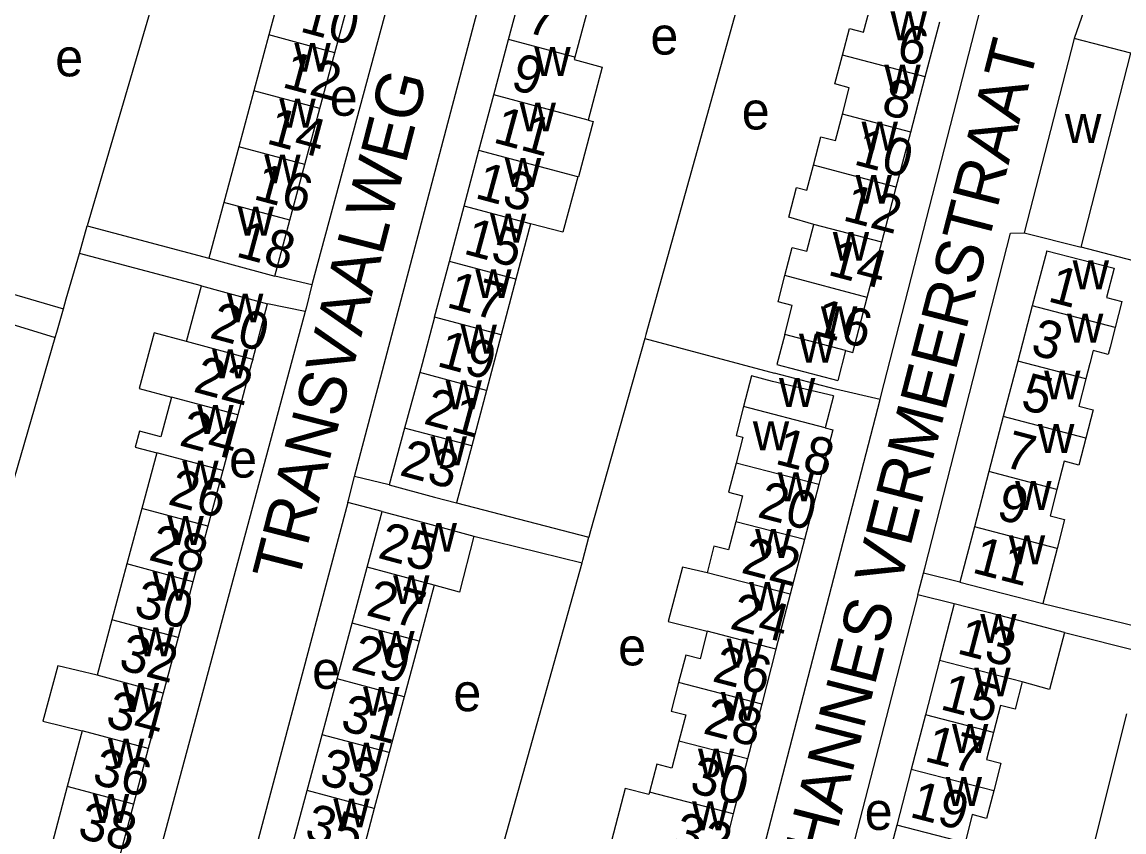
# Model space of a CAD drawing. Extents: x 163012 to 165277, y 382513 to 383987.
# Drawn here: x 163795.3 to 163912.4, y 383200.2 to 383286.3 of the extents above; entities that cross this region are included whole.
import ezdxf

# ---------------------------------------------------------------- set-up
doc = ezdxf.new("R2010")
doc.units = 0
for name, color, linetype in [('BLT_Basislijn', 7, 'Continuous'), ('BLT_Bebouwing', 7, 'Continuous'), ('BLT_Centroide', 7, 'Continuous'), ('BLT_Huisnummer', 7, 'Continuous'), ('BLT_Huisnummer_ tussenligend', 7, 'Continuous'), ('BLT_Onderverdeling_panden', 7, 'Continuous'), ('BLT_Straatnaam', 7, 'Continuous')]:
    doc.layers.add(name, color=color, linetype=linetype)

msp = doc.modelspace()

# ---------------------------------------------------------------- linework, layer by layer
at = {"layer": 'BLT_Basislijn'}
for p, q in [((163817.44, 383316.53), (163802.21, 383264.65)), ((163909.37, 383291.03), (163907.14, 383284.56)), ((163801.39, 383261.7), (163802.21, 383264.65)), ((163802.21, 383264.65), (163815.15, 383261.2)), ((163814.35, 383258.26), (163801.39, 383261.7)), ((163915.64, 383260.36), (163907.87, 383262.37)), ((163826.11, 383258.39), (163822.16, 383259.31)), ((163789.27, 383258.89), (163799.68, 383255.82)), ((163785.34, 383256.88), (163798.81, 383252.77)), ((163825.38, 383255.54), (163821.4, 383256.37)), ((163785.09, 383205.63), (163798.81, 383252.77)), ((163861.49, 383252.69), (163875.3, 383248.99)), ((163834.31, 383237.11), (163830.64, 383238.01)), ((163833.57, 383234.29), (163829.92, 383235.25)), ((163841.47, 383235.19), (163855.55, 383231.55)), ((163843.33, 383231.67), (163854.82, 383228.82)), ((163840.86, 383178.81), (163854.82, 383228.82)), ((163894.99, 383226.78), (163891.12, 383227.74)), ((163894.39, 383224.46), (163890.52, 383225.42)), ((163903.81, 383224.49), (163915.06, 383221.77)), ((163906.11, 383221.42), (163914.43, 383219.32)), ((163909.31, 383199.05), (163912.74, 383212.77))]:
    msp.add_line(p, q, dxfattribs=at)
for points in [[(163840.47, 383311.66), (163826.38, 383259.43), (163826.11, 383258.39)], [(163830.64, 383238.01), (163830.81, 383238.67), (163849.46, 383309.26)], [(163875.6, 383303.33), (163861.61, 383253.11), (163861.49, 383252.69)], [(163886.51, 383246.19), (163886.63, 383246.66), (163898.8, 383294.11), (163899.25, 383297.48)], [(163891.12, 383227.74), (163891.25, 383228.24), (163900.39, 383263.88), (163901.83, 383263.92)], [(163799.68, 383255.82), (163799.99, 383256.88), (163801.39, 383261.7)], [(163826.11, 383258.39), (163825.48, 383255.9), (163825.38, 383255.54)], [(163798.81, 383252.77), (163798.98, 383253.35), (163799.68, 383255.82)], [(163825.38, 383255.54), (163806.41, 383184.98), (163806.33, 383184.51)], [(163861.49, 383252.69), (163855.73, 383232.22), (163855.55, 383231.55)], [(163886.51, 383246.19), (163881.76, 383247.29), (163875.3, 383248.99)], [(163867.61, 383171.92), (163867.73, 383172.49), (163869.27, 383179.64), (163886.51, 383246.19)], [(163829.92, 383235.25), (163829.99, 383235.49), (163830.64, 383238.01)], [(163829.92, 383235.25), (163815.82, 383182.22), (163815.72, 383181.65)], [(163854.82, 383228.82), (163854.9, 383229.11), (163855.55, 383231.55)], [(163890.52, 383225.42), (163890.6, 383225.71), (163891.12, 383227.74)], [(163890.52, 383225.42), (163878.52, 383178.89), (163878.45, 383178.55)]]:
    msp.add_lwpolyline(points, dxfattribs=at)
at = {"layer": 'BLT_Bebouwing'}
for p, q in [((163823.12, 383290.88), (163821.53, 383284.95)), ((163847.01, 383284.48), (163848.58, 383290.38)), ((163828.54, 383283.06), (163830.14, 383289)), ((163891.31, 383280.48), (163892.85, 383286.34)), ((163821.53, 383284.95), (163819.93, 383279.01)), ((163845.43, 383278.57), (163847.01, 383284.48)), ((163907.14, 383284.56), (163901.83, 383263.92)), ((163826.94, 383277.12), (163828.54, 383283.06)), ((163889.77, 383274.62), (163891.31, 383280.48)), ((163819.93, 383279.01), (163818.34, 383273.07)), ((163843.86, 383272.67), (163845.43, 383278.57)), ((163825.35, 383271.19), (163826.94, 383277.12)), ((163888.22, 383268.77), (163889.77, 383274.62)), ((163818.34, 383273.07), (163816.74, 383267.14)), ((163842.29, 383266.76), (163843.86, 383272.67)), ((163823.75, 383265.25), (163825.35, 383271.19)), ((163886.68, 383262.91), (163888.22, 383268.77)), ((163816.74, 383267.14), (163815.15, 383261.2)), ((163840.72, 383260.86), (163842.29, 383266.76)), ((163822.16, 383259.31), (163823.75, 383265.25)), ((163901.83, 383263.92), (163907.87, 383262.37)), ((163885.14, 383257.05), (163886.68, 383262.91)), ((163904.23, 383262.01), (163902.69, 383256.14)), ((163839.15, 383254.95), (163840.72, 383260.86)), ((163812.76, 383252.35), (163814.35, 383258.26)), ((163819.81, 383250.46), (163821.4, 383256.37)), ((163902.69, 383256.14), (163901.15, 383250.27)), ((163882.84, 383251.4), (163882, 383248.2)), ((163901.15, 383250.27), (163899.61, 383244.4)), ((163837.57, 383249.05), (163835.96, 383243.15)), ((163881.57, 383246.57), (163880.68, 383243.19)), ((163818.22, 383244.55), (163816.64, 383238.64)), ((163899.61, 383244.4), (163898.07, 383238.53)), ((163835.96, 383243.15), (163834.31, 383237.11)), ((163809.6, 383240.53), (163808.01, 383234.61)), ((163843.1, 383241.25), (163841.47, 383235.19)), ((163816.64, 383238.64), (163815.05, 383232.72)), ((163898.07, 383238.53), (163896.53, 383232.65)), ((163879.98, 383237.14), (163878.47, 383231.31)), ((163808.01, 383234.61), (163806.43, 383228.7)), ((163831.98, 383228.36), (163833.57, 383234.29)), ((163815.05, 383232.72), (163813.46, 383226.81)), ((163896.53, 383232.65), (163894.99, 383226.78)), ((163878.47, 383231.31), (163876.95, 383225.48)), ((163806.43, 383228.7), (163804.85, 383222.78)), ((163830.39, 383222.42), (163831.98, 383228.36)), ((163813.46, 383226.81), (163811.88, 383220.9)), ((163839.11, 383226.45), (163837.51, 383220.51)), ((163876.95, 383225.48), (163875.44, 383219.64)), ((163894.39, 383224.46), (163892.83, 383218.45)), ((163804.85, 383222.78), (163803.26, 383216.87)), ((163828.79, 383216.49), (163830.39, 383222.42)), ((163811.88, 383220.9), (163810.29, 383214.98)), ((163837.51, 383220.51), (163835.92, 383214.58)), ((163875.44, 383219.64), (163873.92, 383213.81)), ((163892.83, 383218.45), (163891.33, 383212.67)), ((163827.2, 383210.55), (163828.79, 383216.49)), ((163810.29, 383214.98), (163808.71, 383209.07)), ((163835.92, 383214.58), (163834.33, 383208.64)), ((163873.92, 383213.81), (163872.41, 383207.97)), ((163891.33, 383212.67), (163889.82, 383206.86)), ((163801.68, 383210.96), (163800.1, 383205.04)), ((163825.61, 383204.62), (163827.2, 383210.55)), ((163808.71, 383209.07), (163807.12, 383203.16)), ((163834.33, 383208.64), (163832.74, 383202.7)), ((163872.41, 383207.97), (163870.89, 383202.14)), ((163889.82, 383206.86), (163888.28, 383200.94)), ((163800.1, 383205.04), (163798.51, 383199.13)), ((163824.02, 383198.68), (163825.61, 383204.62)), ((163807.12, 383203.16), (163805.54, 383197.24)), ((163832.74, 383202.7), (163831.14, 383196.77)), ((163870.89, 383202.14), (163869.38, 383196.31)), ((163888.28, 383200.94), (163886.8, 383195.26))]:
    msp.add_line(p, q, dxfattribs=at)
for points in [[(163855.64, 383288.5), (163854.07, 383282.6)], [(163882.5, 383282.8), (163883.26, 383285.65), (163884.76, 383285.25), (163885.55, 383288.26)], [(163907.87, 383262.37), (163913.18, 383283.01), (163907.14, 383284.56)], [(163854.07, 383282.6), (163854, 383282.33), (163856.98, 383281.54), (163855.49, 383275.89)], [(163882.51, 383276.53), (163883.24, 383279.34), (163881.7, 383279.74), (163882.5, 383282.8)], [(163855.49, 383275.89), (163856.02, 383275.75), (163854.45, 383269.85), (163854.36, 383269.87)], [(163879.42, 383271.09), (163880.22, 383274.13), (163880.64, 383274.02), (163881.77, 383273.72), (163882.51, 383276.53)], [(163879.46, 383264.81), (163876.8, 383265.59), (163877.62, 383268.72), (163878.72, 383268.43), (163879.42, 383271.09)], [(163854.36, 383269.87), (163852.79, 383263.97), (163849.36, 383264.88)], [(163849.36, 383264.88), (163847.79, 383258.97)], [(163876.39, 383259.36), (163877.17, 383262.36), (163878.71, 383261.95), (163879.46, 383264.81)], [(163904.23, 383262.01), (163911.39, 383260.14), (163910.58, 383257.03), (163912.22, 383256.6), (163911.5, 383253.83)], [(163815.15, 383261.2), (163817.33, 383260.61), (163822.16, 383259.31)], [(163847.79, 383258.97), (163846.22, 383253.07)], [(163876.37, 383253.1), (163877.18, 383256.19), (163875.66, 383256.59), (163876.39, 383259.36)], [(163814.35, 383258.26), (163816.57, 383257.66), (163821.4, 383256.37)], [(163882.84, 383251.4), (163883.6, 383251.2), (163885.14, 383257.05)], [(163839.15, 383254.95), (163837.82, 383249.99), (163837.57, 383249.05)], [(163812.76, 383252.35), (163809.34, 383253.27), (163807.75, 383247.37), (163811.18, 383246.44)], [(163911.5, 383253.83), (163910.96, 383251.77), (163910.76, 383250.99), (163909.18, 383251.4), (163908.82, 383250), (163908.39, 383248.37)], [(163846.22, 383253.07), (163844.66, 383247.16)], [(163876.37, 383253.1), (163875.54, 383249.9), (163882, 383248.2)], [(163819.81, 383250.46), (163819.69, 383250), (163818.22, 383244.55)], [(163881.57, 383246.57), (163875.08, 383248.11), (163872.84, 383248.69), (163872, 383245.44)], [(163908.39, 383248.37), (163907.64, 383245.48), (163909.18, 383245.08), (163908.4, 383242.09)], [(163811.18, 383246.44), (163810.06, 383242.22), (163807.78, 383242.83), (163807.33, 383241.13), (163809.6, 383240.53)], [(163844.66, 383247.16), (163843.1, 383241.25)], [(163872, 383245.44), (163871.2, 383242.36), (163871.91, 383242.18), (163871.2, 383239.43)], [(163880.68, 383243.19), (163881.5, 383242.97), (163880.64, 383239.69), (163879.98, 383237.14)], [(163908.4, 383242.09), (163907.65, 383239.21), (163906.08, 383239.62), (163905.3, 383236.63)], [(163871.2, 383239.43), (163870.39, 383236.32), (163871.89, 383235.93), (163871.18, 383233.2)], [(163834.31, 383237.11), (163839.14, 383235.82), (163841.47, 383235.19)], [(163905.3, 383236.63), (163904.58, 383233.83), (163906.13, 383233.43), (163905.33, 383230.35)], [(163833.57, 383234.29), (163838.4, 383232.99), (163843.33, 383231.67)], [(163871.18, 383233.2), (163870.4, 383230.21), (163868.85, 383230.61), (163868.11, 383227.77)], [(163843.33, 383231.67), (163841.78, 383225.69), (163839.11, 383226.45)], [(163905.33, 383230.35), (163903.81, 383224.49)], [(163868.11, 383227.77), (163865.49, 383228.38), (163863.98, 383222.57), (163868.13, 383221.54)], [(163894.99, 383226.78), (163899.52, 383225.61), (163903.81, 383224.49)], [(163906.11, 383221.42), (163899.23, 383223.21), (163894.39, 383224.46)], [(163868.13, 383221.54), (163867.37, 383218.62), (163865.84, 383219.02), (163865.08, 383216.1)], [(163906.11, 383221.42), (163904.53, 383215.35), (163901.62, 383216.17)], [(163803.26, 383216.87), (163799.08, 383217.87), (163797.5, 383211.98), (163801.68, 383210.96)], [(163865.08, 383216.1), (163864.29, 383213.06), (163865.84, 383212.66), (163865.11, 383209.87)], [(163901.62, 383216.17), (163900.86, 383213.27), (163899.32, 383213.67), (163898.58, 383210.79)], [(163865.11, 383209.87), (163864.36, 383206.99), (163862.77, 383207.4), (163862, 383204.45)], [(163898.58, 383210.79), (163897.83, 383207.91), (163899.35, 383207.51), (163898.59, 383204.58)], [(163862, 383204.45), (163861.93, 383204.18), (163859.4, 383204.83), (163857.97, 383199.26), (163862.03, 383198.21)], [(163898.59, 383204.58), (163897.83, 383201.65), (163896.31, 383202.05), (163895.54, 383199.05)]]:
    msp.add_lwpolyline(points, dxfattribs=at)
at = {"layer": 'BLT_Onderverdeling_panden'}
for p, q in [((163828.54, 383283.06), (163821.53, 383284.95)), ((163854.07, 383282.6), (163847.01, 383284.48)), ((163891.31, 383280.48), (163882.5, 383282.8)), ((163826.94, 383277.12), (163819.93, 383279.01)), ((163855.49, 383275.89), (163845.43, 383278.57)), ((163889.77, 383274.62), (163882.51, 383276.53)), ((163825.35, 383271.19), (163818.34, 383273.07)), ((163854.36, 383269.87), (163843.86, 383272.67)), ((163888.22, 383268.77), (163879.42, 383271.09)), ((163823.75, 383265.25), (163816.74, 383267.14)), ((163849.36, 383264.88), (163842.29, 383266.76)), ((163886.68, 383262.91), (163879.46, 383264.81)), ((163847.79, 383258.97), (163840.72, 383260.86)), ((163885.14, 383257.05), (163876.39, 383259.36)), ((163911.5, 383253.83), (163902.69, 383256.14)), ((163846.22, 383253.07), (163839.15, 383254.95)), ((163819.81, 383250.46), (163812.76, 383252.35)), ((163882.84, 383251.4), (163876.37, 383253.1)), ((163908.39, 383248.37), (163901.15, 383250.27)), ((163844.66, 383247.16), (163837.57, 383249.05)), ((163818.22, 383244.55), (163811.18, 383246.44)), ((163880.68, 383243.18), (163872, 383245.44)), ((163908.4, 383242.09), (163899.61, 383244.4)), ((163843.1, 383241.25), (163835.96, 383243.15)), ((163816.64, 383238.64), (163809.6, 383240.53)), ((163879.98, 383237.14), (163871.2, 383239.43)), ((163905.3, 383236.63), (163898.07, 383238.53)), ((163815.05, 383232.72), (163808.01, 383234.61)), ((163878.47, 383231.31), (163871.18, 383233.2)), ((163905.33, 383230.35), (163896.53, 383232.65)), ((163813.46, 383226.81), (163806.43, 383228.7)), ((163839.11, 383226.45), (163831.98, 383228.36)), ((163876.95, 383225.48), (163868.11, 383227.77)), ((163811.88, 383220.9), (163804.85, 383222.78)), ((163837.51, 383220.51), (163830.39, 383222.42)), ((163875.44, 383219.64), (163868.13, 383221.54)), ((163901.62, 383216.17), (163892.83, 383218.45)), ((163810.29, 383214.98), (163803.26, 383216.87)), ((163835.92, 383214.58), (163828.79, 383216.49)), ((163873.92, 383213.81), (163865.08, 383216.1)), ((163898.58, 383210.79), (163891.33, 383212.67)), ((163808.71, 383209.07), (163801.68, 383210.96)), ((163834.33, 383208.64), (163827.2, 383210.55)), ((163872.41, 383207.97), (163865.11, 383209.87)), ((163898.59, 383204.58), (163889.82, 383206.86)), ((163807.12, 383203.16), (163800.1, 383205.04)), ((163832.74, 383202.7), (163825.61, 383204.62)), ((163870.89, 383202.14), (163862, 383204.45)), ((163895.54, 383199.05), (163888.28, 383200.94))]:
    msp.add_line(p, q, dxfattribs=at)

# ---------------------------------------------------------------- texts
at = {"layer": 'BLT_Centroide'}
for s, p in [('w', (163887.62, 383284.38)), ('e', (163862.09, 383282.87)), ('e', (163798.81, 383280.55)), ('w', (163824.24, 383281.03)), ('w', (163849.75, 383280.59)), ('w', (163886.96, 383278.72)), ('e', (163828, 383276.36)), ('w', (163822.64, 383275.09)), ('w', (163848.18, 383274.69)), ('e', (163871.8, 383274.9)), ('w', (163884.54, 383272.66)), ('w', (163906.17, 383273.47)), ('w', (163821.04, 383269.16)), ('w', (163846.61, 383268.78)), ('w', (163883.9, 383267)), ('w', (163818.2, 383263.62)), ('w', (163845.04, 383262.88)), ('w', (163881.48, 383260.94)), ('w', (163906.98, 383257.91)), ('w', (163843.47, 383256.97)), ('w', (163817.08, 383254.38)), ('w', (163880.22, 383253.02)), ('w', (163906.38, 383252.25)), ('w', (163841.9, 383251.06)), ('w', (163877.89, 383250.11)), ('w', (163815.49, 383248.44)), ('w', (163875.76, 383245.41)), ('w', (163903.95, 383246.19)), ('w', (163840.31, 383245.16)), ('w', (163813.91, 383242.53)), ('w', (163872.98, 383240.8)), ('w', (163903.3, 383240.5)), ('w', (163838.71, 383239.19)), ('e', (163817.3, 383237.89)), ('w', (163812.32, 383236.62)), ('w', (163875.63, 383235.38)), ('w', (163900.87, 383234.44)), ('w', (163810.74, 383230.72)), ('w', (163837.66, 383230)), ('w', (163873.23, 383229.34)), ('w', (163900.19, 383228.66)), ('w', (163809.16, 383224.81)), ('w', (163834.74, 383224.44)), ('w', (163872.59, 383223.72)), ('w', (163897.16, 383220.31)), ('w', (163807.57, 383218.88)), ('w', (163833.15, 383218.5)), ('e', (163858.66, 383217.92)), ('w', (163870.2, 383217.69)), ('e', (163826.13, 383215.43)), ('w', (163896.52, 383214.62)), ('w', (163805.98, 383212.97)), ('w', (163831.55, 383212.56)), ('e', (163841.14, 383213.05)), ('w', (163869.57, 383212.03)), ('w', (163894.15, 383208.62)), ('w', (163804.41, 383207.06)), ('w', (163829.96, 383206.62)), ('w', (163867.15, 383206)), ('w', (163893.48, 383202.97)), ('w', (163802.81, 383201.16)), ('w', (163828.38, 383200.69)), ('w', (163866.52, 383200.38)), ('e', (163884.87, 383200.43))]:
    msp.add_text(s, height=4, dxfattribs=at).set_placement(p)
at = {"layer": 'BLT_Huisnummer'}
for s, rotation, p in [('10', 344.9512, (163824.7, 383285.35)), ('6', 345.2587, (163888.08, 383282.34)), ('9', 344.8974, (163847.1, 383279.23)), ('14', 344.9512, (163821.14, 383273.45)), ('10', 345.2512, (163883.58, 383271.22)), ('13', 344.8974, (163843.31, 383267.65)), ('18', 344.9494, (163817.9, 383261.43)), ('14', 345.2558, (163880.82, 383259.47)), ('1', 345.3109, (163904.21, 383256.66)), ('17', 344.8949, (163840.28, 383256.05)), ('20', 344.9852, (163815.1, 383252.79)), ('5', 345.3097, (163901.32, 383245.22)), ('24', 344.9861, (163811.87, 383241.35)), ('18', 345.4451, (163875.21, 383239.39)), ('23', 344.98, (163835.29, 383238.18)), ('28', 344.9829, (163808.61, 383229.17)), ('25', 344.9851, (163832.98, 383229.38)), ('22', 345.4404, (163871.61, 383227.8)), ('11', 345.4379, (163896.16, 383227.82)), ('13', 345.4313, (163894.55, 383219.23)), ('32', 344.9859, (163805.42, 383217.56)), ('29', 344.9831, (163830.13, 383217.48)), ('26', 345.4404, (163868.54, 383216.26)), ('17', 345.4248, (163891.09, 383207.78)), ('36', 344.9874, (163802.61, 383205.4)), ('33', 344.9791, (163826.75, 383205.36)), ('30', 345.4455, (163866.13, 383204.49))]:
    msp.add_text(s, height=4, rotation=rotation, dxfattribs=at).set_placement(p)
at = {"layer": 'BLT_Huisnummer_ tussenligend'}
for s, rotation, p in [('7', 344.8925, (163848.75, 383285.29)), ('12', 344.9512, (163822.81, 383279.43)), ('8', 345.2587, (163886.5, 383276.6)), ('11', 344.8974, (163845.24, 383273.56)), ('16', 344.9512, (163819.75, 383267.53)), ('12', 345.2512, (163882.41, 383265.28)), ('15', 344.8974, (163842.09, 383261.73)), ('16', 345.2558, (163879.24, 383253.13)), ('3', 345.3109, (163902.39, 383251.03)), ('19', 344.8949, (163839.25, 383249.78)), ('22', 344.9852, (163813.37, 383247.05)), ('21', 344.8949, (163837.85, 383243.65)), ('7', 345.3097, (163899.52, 383239.09)), ('26', 344.9861, (163810.66, 383235.08)), ('20', 345.4451, (163873.34, 383233.72)), ('9', 345.3097, (163898.74, 383233.54)), ('30', 344.9829, (163807.03, 383223.25)), ('27', 344.9851, (163831.74, 383223.29)), ('24', 345.4404, (163870.41, 383221.86)), ('15', 345.4313, (163892.77, 383213.29)), ('34', 344.9859, (163804.02, 383211.48)), ('31', 344.9831, (163829, 383211.09)), ('28', 345.4404, (163867.56, 383210.72)), ('19', 345.4248, (163889.52, 383201.84)), ('38', 344.9874, (163801.05, 383199.65)), ('35', 344.9791, (163825.18, 383199.44)), ('32', 345.4455, (163864.36, 383198.54))]:
    msp.add_text(s, height=4, rotation=rotation, dxfattribs=at).set_placement(p)
at = {"layer": 'BLT_Straatnaam'}
for s, p in [('JOHANNES VERMEERSTRAAT', (163879.08, 383189.03)), ('TRANSVAALWEG', (163824.59, 383226.49))]:
    msp.add_text(s, height=5, rotation=75.5938, dxfattribs=at).set_placement(p)

doc.saveas('drawing.dxf')
